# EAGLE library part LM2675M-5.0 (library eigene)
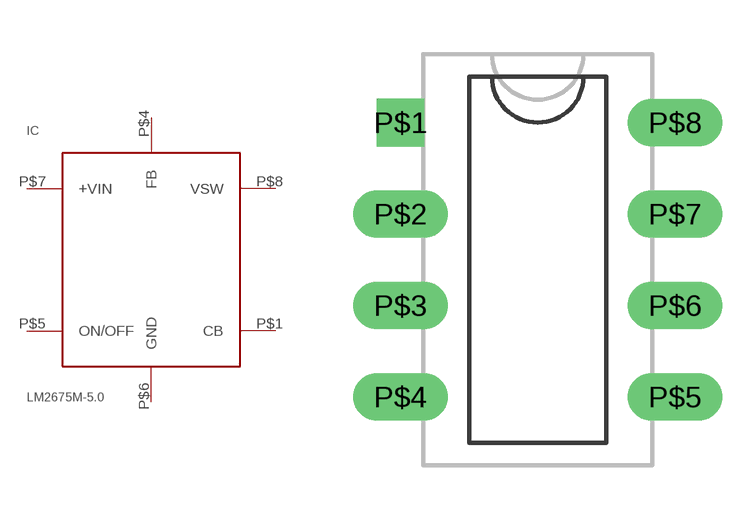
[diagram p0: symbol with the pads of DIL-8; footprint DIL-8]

Designator prefix IC

## LM2675M-5.0  [DIL-8]
P$1  CB
P$4  FB
P$5  ON/OFF
P$6  GND
P$7  +VIN
P$8  VSW

## Footprint DIL-8 (pad centres in mm)
drill 0.813 square: P$1 -3.81,3.81
drill 0.813 long: P$2 -3.81,1.27; P$3 -3.81,-1.27; P$4 -3.81,-3.81; P$5 3.81,-3.81; P$6 3.81,-1.27; P$7 3.81,1.27; P$8 3.81,3.81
